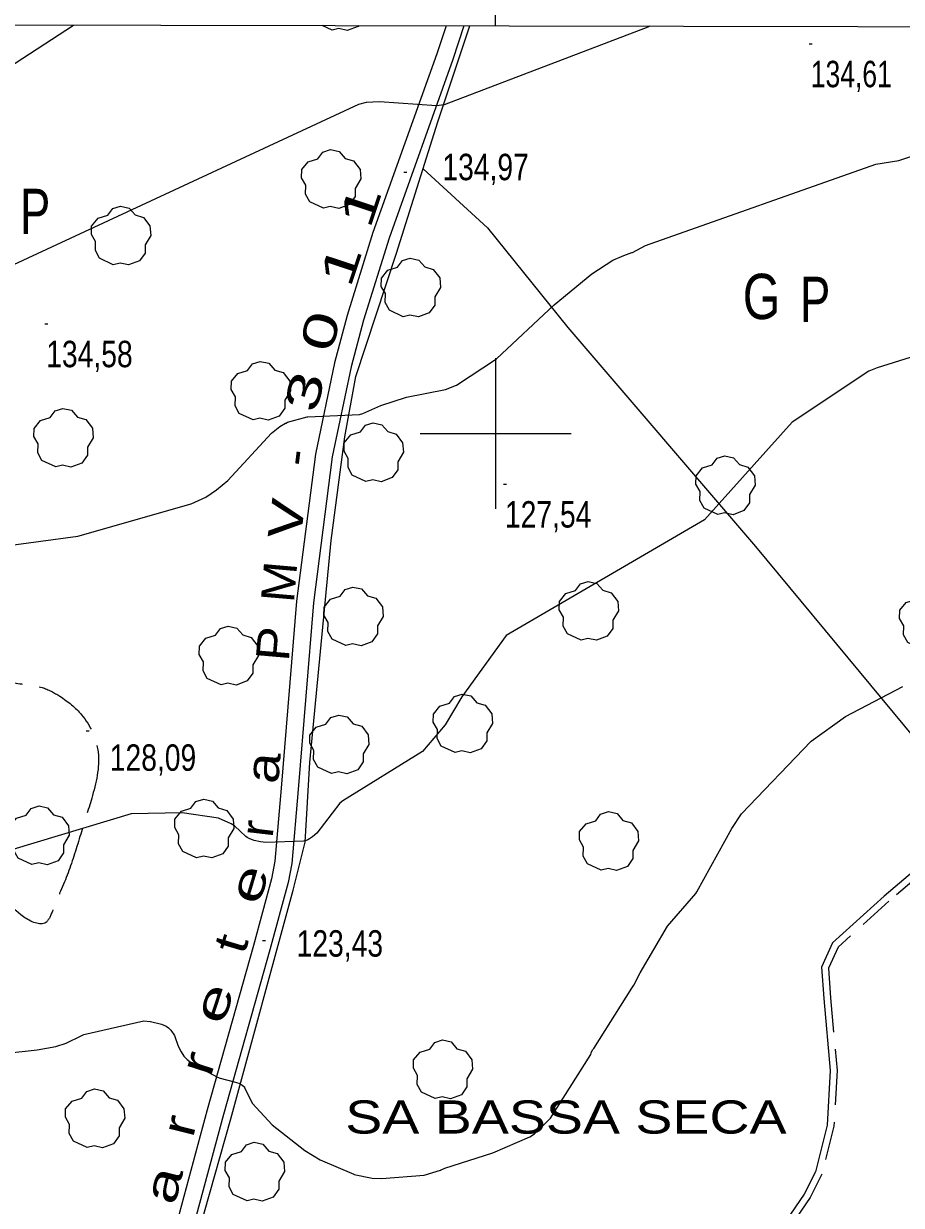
# Model space of a CAD drawing. Extents: x 483843 to 488449, y 4381269 to 4384483.
# Drawn here: x 484343.7 to 484634.4, y 4383744.3 to 4384135.8 of the extents above; entities that cross this region are included whole.
import ezdxf
from ezdxf.enums import TextEntityAlignment as Align

# ---------------------------------------------------------------- set-up
doc = ezdxf.new("R2010")
doc.units = 0
doc.header["$LTSCALE"] = 3.8
doc.linetypes.add('LONG_DASHED', pattern=[7.5, 6, -1.5])
doc.linetypes.add('MEDIUM_DASHED', pattern=[4.5, 3, -1.5])
for name, color, linetype, lineweight in [('1', 7, 'Continuous', 13), ('29', 7, 'Continuous', 13), ('36', 7, 'Continuous', 25), ('38', 7, 'Continuous', 25), ('51', 7, 'Continuous', 13), ('7', 7, 'Continuous', 13), ('8', 7, 'Continuous', 25), ('9', 7, 'Continuous', 13)]:
    doc.layers.add(name, color=color, linetype=linetype, lineweight=lineweight)
doc.layers.add('31', color=7, linetype='Continuous')
doc.layers.add('5', color=7, linetype='Continuous')

msp = doc.modelspace()

# ---------------------------------------------------------------- linework, layer by layer
at = {"layer": '1'}
for p, q in [((484500, 4384135.04), (484500, 4384206.47)), ((484500, 4384025), (484500, 4383975)), ((484475, 4384000), (484525, 4384000))]:
    msp.add_line(p, q, dxfattribs=at)
msp.add_lwpolyline([(484100.5, 4384135.8), (487678, 4384129), (487674.1, 4381816.7), (484095.6, 4381823.6)], close=True, dxfattribs=at)
at = {"layer": '29'}
msp.add_line((484445.85, 4384133.62), (484442.57, 4384135.15), dxfattribs=at)
msp.add_lwpolyline([(484454.7, 4384135.13), (484454.53, 4384134.88), (484450.91, 4384133.54), (484448.14, 4384134.17), (484445.85, 4384133.62)], dxfattribs=at)
for points in [[(484443, 4384074.61), (484438.46, 4384076.73), (484437.05, 4384079.27), (484437.15, 4384082.25), (484435.78, 4384084.66), (484435.82, 4384087.41), (484437.98, 4384090.01), (484441.17, 4384091.01), (484442.82, 4384093.2), (484445.39, 4384094.03), (484448.25, 4384093.38), (484450.2, 4384091.11), (484453.01, 4384090.29), (484455.14, 4384087.44), (484455.38, 4384084.31), (484453.5, 4384081.16), (484453.5, 4384078.48), (484451.68, 4384075.87), (484448.06, 4384074.53), (484445.29, 4384075.16)], [(484373.43, 4384055.91), (484368.89, 4384058.03), (484367.48, 4384060.57), (484367.58, 4384063.55), (484366.21, 4384065.96), (484366.25, 4384068.71), (484368.41, 4384071.31), (484371.6, 4384072.31), (484373.25, 4384074.5), (484375.82, 4384075.33), (484378.68, 4384074.68), (484380.63, 4384072.41), (484383.44, 4384071.59), (484385.57, 4384068.74), (484385.81, 4384065.61), (484383.93, 4384062.46), (484383.93, 4384059.78), (484382.11, 4384057.17), (484378.49, 4384055.83), (484375.72, 4384056.46)], [(484469.38, 4384038.68), (484464.84, 4384040.8), (484463.43, 4384043.34), (484463.53, 4384046.32), (484462.16, 4384048.73), (484462.2, 4384051.48), (484464.36, 4384054.08), (484467.55, 4384055.08), (484469.2, 4384057.27), (484471.77, 4384058.1), (484474.63, 4384057.45), (484476.58, 4384055.18), (484479.39, 4384054.36), (484481.52, 4384051.51), (484481.76, 4384048.38), (484479.88, 4384045.23), (484479.88, 4384042.55), (484478.06, 4384039.94), (484474.44, 4384038.6), (484471.67, 4384039.23)], [(484419.7, 4384004.48), (484415.16, 4384006.6), (484413.75, 4384009.14), (484413.85, 4384012.12), (484412.48, 4384014.53), (484412.52, 4384017.28), (484414.68, 4384019.88), (484417.87, 4384020.88), (484419.52, 4384023.07), (484422.09, 4384023.9), (484424.95, 4384023.25), (484426.9, 4384020.98), (484429.71, 4384020.16), (484431.84, 4384017.31), (484432.08, 4384014.18), (484430.2, 4384011.03), (484430.2, 4384008.35), (484428.38, 4384005.74), (484424.76, 4384004.4), (484421.99, 4384005.03)], [(484354.36, 4383988.9), (484349.82, 4383991.02), (484348.41, 4383993.56), (484348.51, 4383996.54), (484347.14, 4383998.95), (484347.18, 4384001.7), (484349.34, 4384004.3), (484352.53, 4384005.3), (484354.18, 4384007.49), (484356.75, 4384008.32), (484359.61, 4384007.67), (484361.56, 4384005.4), (484364.37, 4384004.58), (484366.5, 4384001.73), (484366.74, 4383998.6), (484364.86, 4383995.45), (484364.86, 4383992.77), (484363.04, 4383990.16), (484359.42, 4383988.82), (484356.65, 4383989.45)], [(484457.1, 4383984.11), (484452.56, 4383986.23), (484451.15, 4383988.77), (484451.25, 4383991.75), (484449.88, 4383994.16), (484449.92, 4383996.91), (484452.08, 4383999.51), (484455.27, 4384000.51), (484456.92, 4384002.7), (484459.49, 4384003.53), (484462.35, 4384002.88), (484464.3, 4384000.61), (484467.11, 4383999.79), (484469.24, 4383996.94), (484469.48, 4383993.81), (484467.6, 4383990.66), (484467.6, 4383987.98), (484465.78, 4383985.37), (484462.16, 4383984.03), (484459.39, 4383984.66)], [(484573.57, 4383973.18), (484569.03, 4383975.3), (484567.62, 4383977.84), (484567.72, 4383980.82), (484566.35, 4383983.23), (484566.39, 4383985.98), (484568.55, 4383988.58), (484571.74, 4383989.58), (484573.39, 4383991.77), (484575.96, 4383992.6), (484578.82, 4383991.95), (484580.77, 4383989.68), (484583.58, 4383988.86), (484585.71, 4383986.01), (484585.95, 4383982.88), (484584.07, 4383979.73), (484584.07, 4383977.05), (484582.25, 4383974.44), (484578.63, 4383973.1), (484575.86, 4383973.73)], [(484528.32, 4383931.55), (484523.78, 4383933.67), (484522.37, 4383936.21), (484522.47, 4383939.19), (484521.1, 4383941.6), (484521.14, 4383944.35), (484523.3, 4383946.95), (484526.49, 4383947.95), (484528.14, 4383950.14), (484530.71, 4383950.97), (484533.57, 4383950.32), (484535.52, 4383948.05), (484538.33, 4383947.23), (484540.46, 4383944.38), (484540.7, 4383941.25), (484538.82, 4383938.1), (484538.82, 4383935.42), (484537, 4383932.81), (484533.38, 4383931.47), (484530.61, 4383932.1)], [(484450.39, 4383929.71), (484445.85, 4383931.83), (484444.44, 4383934.37), (484444.54, 4383937.35), (484443.17, 4383939.76), (484443.21, 4383942.51), (484445.37, 4383945.11), (484448.56, 4383946.11), (484450.21, 4383948.3), (484452.78, 4383949.13), (484455.64, 4383948.48), (484457.59, 4383946.21), (484460.4, 4383945.39), (484462.53, 4383942.54), (484462.77, 4383939.41), (484460.89, 4383936.26), (484460.89, 4383933.58), (484459.07, 4383930.97), (484455.45, 4383929.63), (484452.68, 4383930.26)], [(484641, 4383928.62), (484636.46, 4383930.74), (484635.05, 4383933.28), (484635.15, 4383936.26), (484633.78, 4383938.67), (484633.82, 4383941.42), (484635.98, 4383944.02), (484639.17, 4383945.02), (484640.82, 4383947.21), (484643.39, 4383948.04), (484646.25, 4383947.39), (484648.2, 4383945.12), (484651.01, 4383944.3), (484653.14, 4383941.45), (484653.38, 4383938.32), (484651.5, 4383935.17), (484651.5, 4383932.49), (484649.68, 4383929.88), (484646.06, 4383928.54), (484643.29, 4383929.17)], [(484409.1, 4383916.75), (484404.56, 4383918.87), (484403.15, 4383921.41), (484403.25, 4383924.39), (484401.88, 4383926.8), (484401.92, 4383929.55), (484404.08, 4383932.15), (484407.27, 4383933.15), (484408.92, 4383935.34), (484411.49, 4383936.17), (484414.35, 4383935.52), (484416.3, 4383933.25), (484419.11, 4383932.43), (484421.24, 4383929.58), (484421.48, 4383926.45), (484419.6, 4383923.3), (484419.6, 4383920.62), (484417.78, 4383918.01), (484414.16, 4383916.67), (484411.39, 4383917.3)], [(484486.58, 4383894.26), (484482.04, 4383896.38), (484480.63, 4383898.92), (484480.73, 4383901.9), (484479.36, 4383904.31), (484479.4, 4383907.06), (484481.56, 4383909.66), (484484.75, 4383910.66), (484486.4, 4383912.85), (484488.97, 4383913.68), (484491.83, 4383913.03), (484493.78, 4383910.76), (484496.59, 4383909.94), (484498.72, 4383907.09), (484498.96, 4383903.96), (484497.08, 4383900.81), (484497.08, 4383898.13), (484495.26, 4383895.52), (484491.64, 4383894.18), (484488.87, 4383894.81)], [(484445.67, 4383887.3), (484441.13, 4383889.42), (484439.72, 4383891.96), (484439.82, 4383894.94), (484438.45, 4383897.35), (484438.49, 4383900.1), (484440.65, 4383902.7), (484443.84, 4383903.7), (484445.49, 4383905.89), (484448.06, 4383906.72), (484450.92, 4383906.07), (484452.87, 4383903.8), (484455.68, 4383902.98), (484457.81, 4383900.13), (484458.05, 4383897), (484456.17, 4383893.85), (484456.17, 4383891.17), (484454.35, 4383888.56), (484450.73, 4383887.22), (484447.96, 4383887.85)], [(484400.98, 4383859.44), (484396.44, 4383861.56), (484395.03, 4383864.1), (484395.13, 4383867.08), (484393.76, 4383869.49), (484393.8, 4383872.24), (484395.96, 4383874.84), (484399.15, 4383875.84), (484400.8, 4383878.03), (484403.37, 4383878.86), (484406.23, 4383878.21), (484408.18, 4383875.94), (484410.99, 4383875.12), (484413.12, 4383872.27), (484413.36, 4383869.14), (484411.48, 4383865.99), (484411.48, 4383863.31), (484409.66, 4383860.7), (484406.04, 4383859.36), (484403.27, 4383859.99)], [(484346.44, 4383857.19), (484341.9, 4383859.31), (484340.49, 4383861.85), (484340.59, 4383864.83), (484339.22, 4383867.24), (484339.26, 4383869.99), (484341.42, 4383872.59), (484344.61, 4383873.59), (484346.26, 4383875.78), (484348.83, 4383876.61), (484351.69, 4383875.96), (484353.64, 4383873.69), (484356.45, 4383872.87), (484358.58, 4383870.02), (484358.82, 4383866.89), (484356.94, 4383863.74), (484356.94, 4383861.06), (484355.12, 4383858.45), (484351.5, 4383857.11), (484348.73, 4383857.74)], [(484534.98, 4383855.31), (484530.44, 4383857.43), (484529.03, 4383859.97), (484529.13, 4383862.95), (484527.76, 4383865.36), (484527.8, 4383868.11), (484529.96, 4383870.71), (484533.15, 4383871.71), (484534.8, 4383873.9), (484537.37, 4383874.73), (484540.23, 4383874.08), (484542.18, 4383871.81), (484544.99, 4383870.99), (484547.12, 4383868.14), (484547.36, 4383865.01), (484545.48, 4383861.86), (484545.48, 4383859.18), (484543.66, 4383856.57), (484540.04, 4383855.23), (484537.27, 4383855.86)], [(484480.02, 4383779.66), (484475.48, 4383781.78), (484474.07, 4383784.32), (484474.17, 4383787.3), (484472.8, 4383789.71), (484472.84, 4383792.46), (484475, 4383795.06), (484478.19, 4383796.06), (484479.84, 4383798.25), (484482.41, 4383799.08), (484485.27, 4383798.43), (484487.22, 4383796.16), (484490.03, 4383795.34), (484492.16, 4383792.49), (484492.4, 4383789.36), (484490.52, 4383786.21), (484490.52, 4383783.53), (484488.7, 4383780.92), (484485.08, 4383779.58), (484482.31, 4383780.21)], [(484364.82, 4383763.44), (484360.28, 4383765.56), (484358.87, 4383768.1), (484358.97, 4383771.08), (484357.6, 4383773.49), (484357.64, 4383776.24), (484359.8, 4383778.84), (484362.99, 4383779.84), (484364.64, 4383782.03), (484367.21, 4383782.86), (484370.07, 4383782.21), (484372.02, 4383779.94), (484374.83, 4383779.12), (484376.96, 4383776.27), (484377.2, 4383773.14), (484375.32, 4383769.99), (484375.32, 4383767.31), (484373.5, 4383764.7), (484369.88, 4383763.36), (484367.11, 4383763.99)], [(484417.71, 4383745.74), (484413.17, 4383747.86), (484411.76, 4383750.4), (484411.86, 4383753.38), (484410.49, 4383755.79), (484410.53, 4383758.54), (484412.69, 4383761.14), (484415.88, 4383762.14), (484417.53, 4383764.33), (484420.1, 4383765.16), (484422.96, 4383764.51), (484424.91, 4383762.24), (484427.72, 4383761.42), (484429.85, 4383758.57), (484430.09, 4383755.44), (484428.21, 4383752.29), (484428.21, 4383749.61), (484426.39, 4383747), (484422.77, 4383745.66), (484420, 4383746.29)]]:
    msp.add_lwpolyline(points, close=True, dxfattribs=at)
at = {"layer": '36'}
for points in [[(484483.62, 4384135.07), (484480.51, 4384125.78), (484459.4, 4384066.54), (484450.92, 4384039.11), (484446.7, 4384023.41), (484440.33, 4383993.19), (484434.13, 4383944.43), (484428.99, 4383882.46), (484426.96, 4383858.28), (484425.86, 4383852.48), (484419.89, 4383830.41), (484404.46, 4383775.89), (484385.15, 4383704.18), (484371.21, 4383651.69), (484365.59, 4383632.66), (484364.18, 4383627.75), (484361.64, 4383623.03), (484356.29, 4383615.94), (484349.52, 4383609.16), (484338.85, 4383601.2)], [(484489.54, 4384135.06), (484485.82, 4384123.95), (484464.73, 4384064.76), (484456.32, 4384037.55), (484452.16, 4384022.11), (484445.88, 4383992.25), (484439.72, 4383943.85), (484434.59, 4383882), (484432.54, 4383857.52), (484431.34, 4383851.22), (484425.3, 4383828.91), (484409.87, 4383774.4), (484390.58, 4383702.73), (484376.62, 4383650.17), (484370.9, 4383630.79), (484368.78, 4383624.62), (484366.56, 4383620.22), (484360.54, 4383612.24), (484358.1, 4383609.8)]]:
    msp.add_lwpolyline(points, dxfattribs=at)
at = {"layer": '38'}
msp.add_lwpolyline([(484640.29, 4383856.59), (484628.72, 4383846.73), (484611.56, 4383831.21), (484607.94, 4383823.23), (484608.66, 4383812.83), (484610.78, 4383788.9), (484609.79, 4383770.82), (484605.93, 4383755.38), (484602.23, 4383748.02), (484587.21, 4383726.05)], dxfattribs=at)
at = {"layer": '38', "linetype": 'MEDIUM_DASHED'}
msp.add_lwpolyline([(484641.47, 4383854.6), (484630.23, 4383845.01), (484613.44, 4383829.84), (484610.26, 4383822.81), (484610.93, 4383813.01), (484613.07, 4383788.94), (484612.05, 4383770.48), (484608.08, 4383754.59), (484604.2, 4383746.86), (484589.36, 4383725.17)], dxfattribs=at)
at = {"layer": '38', "linetype": 'LONG_DASHED'}
msp.add_spline([(484247.72, 4383908.64), (484253.33, 4383919.35), (484264.48, 4383925.01), (484274.86, 4383929.81), (484282.77, 4383933.19), (484294.63, 4383932.81), (484308.38, 4383928.59), (484321.61, 4383925.54), (484327.89, 4383922.19), (484340.71, 4383917.35), (484349.84, 4383915.84), (484355.75, 4383912.92), (484362.94, 4383906.76), (484368.4, 4383894.39), (484366.27, 4383879.17), (484362.63, 4383867.29), (484358.45, 4383854.44), (484353.36, 4383842), (484351.06, 4383838), (484343.65, 4383839.9), (484334.08, 4383851.41), (484323.52, 4383863.21), (484318.9, 4383869.15), (484307.36, 4383875.66), (484292.33, 4383871.38), (484284.58, 4383869.16), (484280.69, 4383867.11)], degree=3, dxfattribs=at)
at = {"layer": '51'}
for points in [[(484196.78, 4384026.71), (484285.43, 4384086.52), (484360.3, 4384135.31)], [(484389.67, 4383693.04), (484412.38, 4383772.96), (484432.96, 4383848.65), (484436.93, 4383864.62), (484438.49, 4383890.95), (484445.61, 4383964.54), (484450.1, 4383998.92), (484453.76, 4384018.89), (484467.21, 4384059.78), (484480.93, 4384103.22), (484491.47, 4384135.06)], [(484476.02, 4384087.66), (484497.31, 4384068.08), (484523.9, 4384035.08), (484586.12, 4383962.6), (484662.18, 4383870.7)]]:
    msp.add_lwpolyline(points, dxfattribs=at)
at = {"layer": '7'}
for p, q in [((484603.87, 4384129.08), (484604.87, 4384129.08)), ((484469.59, 4384086.56), (484470.59, 4384086.56)), ((484350.72, 4384036.32), (484351.72, 4384036.32)), ((484502.6, 4383983.2), (484503.6, 4383983.2)), ((484364.48, 4383901.47), (484365.48, 4383901.47)), ((484422.81, 4383832.04), (484423.81, 4383832.04))]:
    msp.add_line(p, q, dxfattribs=at)
at = {"layer": '8'}
msp.add_lwpolyline([(484646.4, 4384027.99), (484626.32, 4384021.76), (484623.63, 4384020.63), (484598.2, 4384003.71), (484569.15, 4383971.44), (484503.5, 4383933.05), (484488.84, 4383912.7), (484483.32, 4383903.52), (484475.86, 4383894.66), (484449.38, 4383878.28), (484448.39, 4383877.53), (484440.79, 4383867.58), (484439.38, 4383866.34), (484438.42, 4383865.66), (484437.87, 4383865.36), (484437.02, 4383865.03), (484436.44, 4383864.88), (484423.98, 4383864.53), (484422.19, 4383864.66), (484420.07, 4383865.12), (484418.6, 4383865.67), (484417.78, 4383866.12), (484417.29, 4383866.45), (484413.54, 4383870), (484412.46, 4383870.66), (484408.27, 4383872.52), (484396.22, 4383874.32), (484379.32, 4383873.98), (484331.98, 4383859.71)], dxfattribs=at)
at = {"layer": '9'}
for points in [[(484551.07, 4384134.94), (484550.43, 4384134.59), (484482.98, 4384108.87), (484480.5, 4384108.56), (484461.53, 4384109.9), (484457.17, 4384109.62), (484454.66, 4384109.03), (484329.3, 4384050.84), (484310.26, 4384044.21), (484268.35, 4384040.76), (484174.94, 4384050.39), (484102.66, 4384088.44), (484100.4, 4384088.99)], [(484314.18, 4383959.61), (484361.71, 4383965.96), (484399.26, 4383976.73), (484404.06, 4383978.9), (484404.08, 4383978.93), (484404.09, 4383978.94), (484407.55, 4383981.29), (484411.39, 4383984.47), (484425.8, 4384000.12), (484428.56, 4384002.28), (484430.41, 4384003.38), (484430.6, 4384003.44), (484430.66, 4384003.44), (484430.69, 4384003.43), (484430.72, 4384003.44), (484430.74, 4384003.47), (484430.74, 4384003.48), (484430.75, 4384003.53), (484431.14, 4384003.71), (484437.58, 4384005.55), (484437.76, 4384005.56), (484437.82, 4384005.52), (484437.85, 4384005.51), (484454.94, 4384006.32), (484456.09, 4384006.66), (484462.01, 4384009.26), (484470.46, 4384012.03), (484483.4, 4384014.55), (484487.07, 4384015.97), (484500.27, 4384024.75), (484519.38, 4384042.63), (484531.86, 4384052.88), (484538.87, 4384057.4), (484542.43, 4384058.97), (484542.46, 4384058.98), (484545.17, 4384059.98), (484545.37, 4384060), (484549.7, 4384062.28), (484625.92, 4384089.24), (484633.52, 4384090.48), (484722.2, 4384119.98)], [(484303.95, 4383790.94), (484348.17, 4383795.75), (484354.35, 4383796.86), (484357.86, 4383798.04), (484362.74, 4383800.47), (484363.68, 4383800.88), (484383.53, 4383805.37), (484385.64, 4383805.24), (484385.7, 4383805.2), (484389.36, 4383804.31), (484390.89, 4383803.64), (484391.68, 4383803.12), (484392.16, 4383802.68), (484392.44, 4383802.36), (484393.64, 4383800.56), (484394.87, 4383797.06), (484395.87, 4383795.1), (484396.81, 4383793.75), (484397.87, 4383792.62), (484399.85, 4383791.04), (484407.89, 4383786.74), (484408.8, 4383786.42), (484413.45, 4383785.23), (484414.96, 4383784.75), (484415.97, 4383784.19), (484416.67, 4383783.67), (484416.83, 4383783.5), (484416.87, 4383783.38), (484416.87, 4383783.36), (484416.85, 4383783.36), (484416.84, 4383783.37), (484419.39, 4383778.16), (484426.04, 4383770.94), (484436.8, 4383762.43), (484441.95, 4383759.38), (484453.08, 4383754.59), (484453.09, 4383754.58), (484453.16, 4383754.55), (484459.11, 4383753.32), (484462.38, 4383753.14), (484476.35, 4383754.28), (484481.81, 4383755.95), (484481.84, 4383755.97), (484481.89, 4383756.02), (484482.02, 4383756.1), (484483.23, 4383756.6), (484499.05, 4383761.64), (484511.37, 4383766.98), (484512.93, 4383768.02), (484518.14, 4383773.14), (484531.51, 4383794.28), (484531.63, 4383794.75), (484531.71, 4383794.94), (484532.24, 4383795.87), (484532.54, 4383796.26), (484545.1, 4383816.26), (484545.79, 4383817.23), (484547.86, 4383821.35), (484556.95, 4383836.77), (484566.29, 4383847.65), (484566.64, 4383848.17), (484578.26, 4383869.18), (484581.47, 4383873.97), (484604.48, 4383898.02), (484615.9, 4383906.18), (484634.85, 4383916.12)]]:
    msp.add_lwpolyline(points, dxfattribs=at)

# ---------------------------------------------------------------- texts
at = {"layer": '31'}
for s, width, p in [('P', 0.75, (484347.56, 4384066.06)), ('G', 0.8, (484588.09, 4384037.9)), ('P', 0.75, (484605.83, 4384036.93))]:
    msp.add_text(s, height=15, dxfattribs=dict(at, width=width)).set_placement(p, align=Align.CENTER)
at = {"layer": '5'}
for s, rotation, width, p in [('1', 71.568, 1.6, (484460.44, 4384073.61)), ('1', 71.568, 1.6, (484453.92, 4384054.06)), ('0', 75.433, 1.55, (484447.28, 4384032.52)), ('3', 75.433, 1.55, (484442.08, 4384012.54)), ('-', 83.059, 1.1, (484438.72, 4383991.46)), ('V', 83.059, 1.35, (484436.24, 4383971.04)), ('M', 85.032, 1.1, (484433.79, 4383950.38)), ('P', 85.032, 1.15, (484432.01, 4383929.86)), ('a', 85.032, 1.25, (484428.43, 4383888.78)), ('r', 83.281, 1.1, (484426.44, 4383868.5)), ('e', 73.429, 1.5, (484423.43, 4383849.21)), ('t', 73.429, 1.3, (484417.55, 4383829.47)), ('e', 71.886, 1.55, (484411.72, 4383809.65)), ('r', 71.886, 1.4, (484406.66, 4383789.74)), ('r', 75.964, 1.3, (484400.55, 4383769.43)), ('a', 75.964, 1.45, (484395.2, 4383749.75))]:
    msp.add_text(s, height=10.99, rotation=rotation, dxfattribs=dict(at, width=width)).set_placement(p, align=Align.CENTER)
at = {"layer": '5', "width": 1.25}
msp.add_text('SA BASSA SECA', height=11, dxfattribs=at).set_placement((484450.23, 4383768.05))
at = {"layer": '7'}
for s, width, p in [('134,61', 0.75, (484604.37, 4384114.71)), ('134,97', 0.8, (484482.39, 4384083.91)), ('134,58', 0.8, (484351.22, 4384021.95)), ('127,54', 0.8, (484503.1, 4383968.83)), ('128,09', 0.8, (484372.26, 4383888.25)), ('123,43', 0.8, (484434.12, 4383826.68))]:
    msp.add_text(s, height=8.75, dxfattribs=dict(at, width=width)).set_placement(p)

doc.saveas('drawing.dxf')
